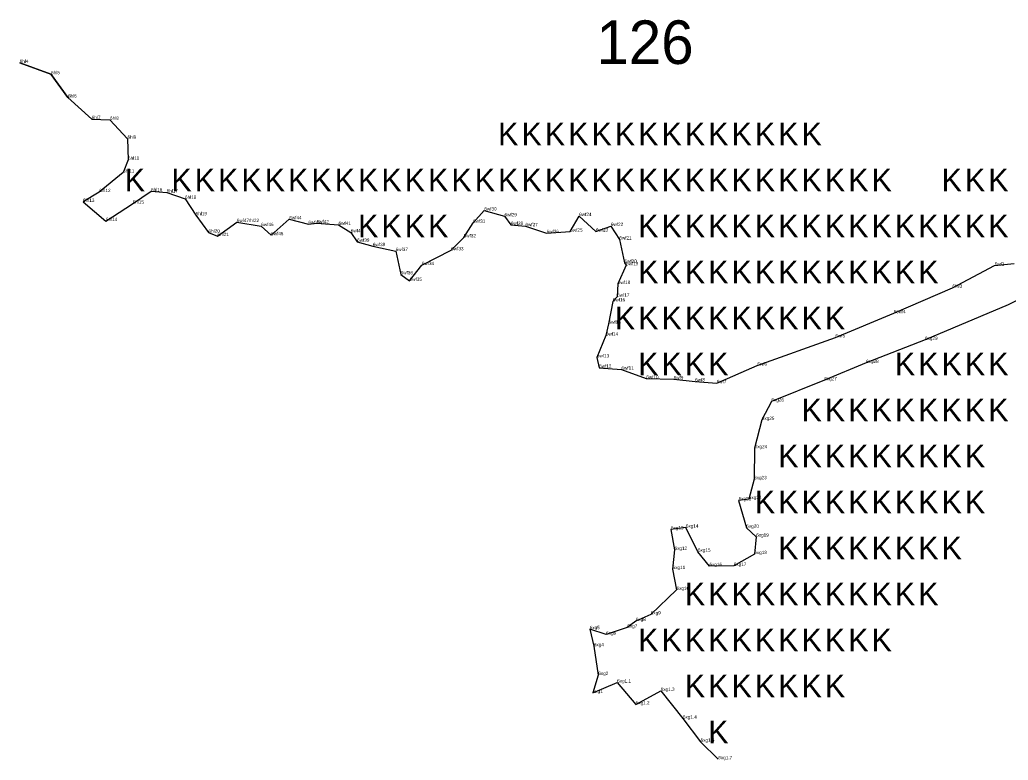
# Model space of a CAD drawing. Extents: x 2072529 to 2268812, y 436423 to 470008.
# Drawn here: x 2151885 to 2153367, y 437861 to 438972 of the extents above; entities that cross this region are included whole.
import ezdxf

# ---------------------------------------------------------------- set-up
doc = ezdxf.new("R2010")
doc.units = 0
for name, color, linetype in [('Old_Level_20', 7, 'Continuous'), ('Old_Level_52', 7, 'Continuous'), ('Old_Level_55', 7, 'Continuous'), ('Old_Level_60', 7, 'Continuous'), ('Old_Level_62', 7, 'Continuous')]:
    doc.layers.add(name, color=color, linetype=linetype)

msp = doc.modelspace()

# ---------------------------------------------------------------- linework, layer by layer
at = {"layer": 'Old_Level_20'}
for p, q in [((2151932.086, 438889.94), (2151932.086, 438889.94)), ((2151932.086, 438889.94), (2151932.086, 438889.94)), ((2151932.086, 438889.94), (2151932.086, 438889.94)), ((2151957.305, 438854.948), (2151957.305, 438854.948)), ((2151957.305, 438854.948), (2151957.305, 438854.948)), ((2151957.305, 438854.948), (2151957.305, 438854.948)), ((2151993.082, 438822.703), (2151993.082, 438822.703)), ((2151993.082, 438822.703), (2151993.082, 438822.703)), ((2151993.082, 438822.703), (2151993.082, 438822.703)), ((2152020.361, 438821.547), (2152020.361, 438821.547)), ((2152046.757, 438793.156), (2152046.757, 438793.156)), ((2152047.495, 438761.53), (2152047.495, 438761.53)), ((2152040.01, 438742.313), (2152040.01, 438742.313)), ((2152004.377, 438713.058), (2152004.377, 438713.058)), ((2152082.016, 438714.429), (2152082.016, 438714.429)), ((2152105.432, 438712.49), (2152105.432, 438712.49)), ((2152132.925, 438703.042), (2152132.925, 438703.042)), ((2151980.215, 438698.474), (2151980.215, 438698.474)), ((2152054.394, 438695.734), (2152054.394, 438695.734)), ((2152148.934, 438678.389), (2152148.934, 438678.389)), ((2152289.336, 438672.405), (2152289.336, 438672.405)), ((2152581.734, 438685.505), (2152581.734, 438685.505)), ((2152581.734, 438685.505), (2152581.734, 438685.505)), ((2152612.078, 438676.759), (2152612.078, 438676.759)), ((2152612.078, 438676.759), (2152612.078, 438676.759)), ((2152724.008, 438677.199), (2152724.008, 438677.199)), ((2152724.008, 438677.199), (2152724.008, 438677.199)), ((2152014.374, 438669.681), (2152014.374, 438669.681)), ((2152210.534, 438668.162), (2152210.534, 438668.162)), ((2152247.263, 438662.066), (2152247.263, 438662.066)), ((2152318.015, 438665.179), (2152318.015, 438665.179)), ((2152330.374, 438666.368), (2152330.374, 438666.368)), ((2152363.146, 438663.945), (2152363.146, 438663.945)), ((2152564.875, 438667.018), (2152564.875, 438667.018)), ((2152564.875, 438667.018), (2152564.875, 438667.018)), ((2152621.518, 438663.89), (2152621.518, 438663.89)), ((2152621.518, 438663.89), (2152621.518, 438663.89)), ((2152643.46, 438661.979), (2152643.46, 438661.979)), ((2152643.46, 438661.979), (2152643.46, 438661.979)), ((2152771.592, 438662.228), (2152771.592, 438662.228)), ((2152771.592, 438662.228), (2152771.592, 438662.228)), ((2152168.125, 438652.279), (2152168.125, 438652.279)), ((2152181.615, 438647.155), (2152181.615, 438647.155)), ((2152262.029, 438648.427), (2152262.029, 438648.427)), ((2152381.634, 438652.722), (2152381.634, 438652.722)), ((2152550.829, 438645.221), (2152550.829, 438645.221)), ((2152675.24, 438651.608), (2152675.24, 438651.608)), ((2152675.24, 438651.608), (2152675.24, 438651.608)), ((2152710.662, 438653.779), (2152710.662, 438653.779)), ((2152710.662, 438653.779), (2152710.662, 438653.779)), ((2152749.073, 438653.975), (2152749.073, 438653.975)), ((2152749.073, 438653.975), (2152749.073, 438653.975)), ((2152391.045, 438638.562), (2152391.045, 438638.562)), ((2152414.676, 438632.035), (2152414.676, 438632.035)), ((2152784.294, 438641.972), (2152784.294, 438641.972)), ((2152784.294, 438641.972), (2152784.294, 438641.972)), ((2152448.851, 438624.645), (2152448.851, 438624.645)), ((2152532.123, 438625.806), (2152532.123, 438625.806)), ((2152487.971, 438603.621), (2152487.971, 438603.621)), ((2152791.953, 438607.04), (2152791.953, 438607.04)), ((2152791.953, 438607.04), (2152791.953, 438607.04)), ((2152794.25, 438603.326), (2152794.25, 438603.326)), ((2152794.25, 438603.326), (2152794.25, 438603.326)), ((2153347.104, 438602.749), (2153347.104, 438602.749)), ((2153347.104, 438602.749), (2153347.104, 438602.749)), ((2152456.335, 438589.708), (2152456.335, 438589.708)), ((2152469.745, 438579.89), (2152469.745, 438579.89)), ((2152782.155, 438575.242), (2152782.155, 438575.242)), ((2152782.155, 438575.242), (2152782.155, 438575.242)), ((2153283.767, 438569.533), (2153283.767, 438569.533)), ((2153283.767, 438569.533), (2153283.767, 438569.533)), ((2152780.938, 438556.129), (2152780.938, 438556.129)), ((2152780.938, 438556.129), (2152780.938, 438556.129)), ((2152774.499, 438549.053), (2152774.499, 438549.053)), ((2152774.499, 438549.053), (2152774.499, 438549.053)), ((2153367.204, 438544.182), (2153367.204, 438544.182)), ((2153367.204, 438544.182), (2153367.204, 438544.182)), ((2153195.696, 438531.422), (2153195.696, 438531.422)), ((2153195.696, 438531.422), (2153195.696, 438531.422)), ((2152768.005, 438515.577), (2152768.005, 438515.577)), ((2152768.005, 438515.577), (2152768.005, 438515.577)), ((2152764.057, 438497.915), (2152764.057, 438497.915)), ((2152764.057, 438497.915), (2152764.057, 438497.915)), ((2153108.314, 438495.075), (2153108.314, 438495.075)), ((2153108.314, 438495.075), (2153108.314, 438495.075)), ((2153242.688, 438491.329), (2153242.688, 438491.329)), ((2153242.688, 438491.329), (2153242.688, 438491.329)), ((2152750.57, 438465.117), (2152750.57, 438465.117)), ((2152750.57, 438465.117), (2152750.57, 438465.117)), ((2152991.182, 438452.732), (2152991.182, 438452.732)), ((2152991.182, 438452.732), (2152991.182, 438452.732)), ((2153154.34, 438456.737), (2153154.34, 438456.737)), ((2153154.34, 438456.737), (2153154.34, 438456.737)), ((2152753.945, 438449.479), (2152753.945, 438449.479)), ((2152753.945, 438449.479), (2152753.945, 438449.479)), ((2152787.432, 438446.808), (2152787.432, 438446.808)), ((2152787.432, 438446.808), (2152787.432, 438446.808)), ((2152824.61, 438433.245), (2152824.61, 438433.245)), ((2152824.61, 438433.245), (2152824.61, 438433.245)), ((2152865.742, 438432.251), (2152865.742, 438432.251)), ((2152865.742, 438432.251), (2152865.742, 438432.251)), ((2152898.033, 438429.104), (2152898.033, 438429.104)), ((2152898.033, 438429.104), (2152898.033, 438429.104)), ((2152930.298, 438426.43), (2152930.298, 438426.43)), ((2152930.298, 438426.43), (2152930.298, 438426.43)), ((2153091.7, 438430.776), (2153091.7, 438430.776)), ((2153091.7, 438430.776), (2153091.7, 438430.776)), ((2153012.335, 438399.042), (2153012.335, 438399.042)), ((2153012.335, 438399.042), (2153012.335, 438399.042)), ((2152997.951, 438371.198), (2152997.951, 438371.198)), ((2152997.951, 438371.198), (2152997.951, 438371.198)), ((2152987.155, 438328.86), (2152987.155, 438328.86)), ((2152987.155, 438328.86), (2152987.155, 438328.86)), ((2152986.406, 438282.382), (2152986.406, 438282.382)), ((2152963.156, 438250.664), (2152963.156, 438250.664)), ((2152963.156, 438250.664), (2152963.156, 438250.664)), ((2152978.542, 438252.567), (2152978.542, 438252.567)), ((2152978.542, 438252.567), (2152978.542, 438252.567)), ((2152861.659, 438207.013), (2152861.659, 438207.013)), ((2152884.089, 438209.695), (2152884.089, 438209.695)), ((2152974.724, 438209.477), (2152974.724, 438209.477)), ((2152989.516, 438196.131), (2152989.516, 438196.131)), ((2152867.037, 438176.333), (2152867.037, 438176.333)), ((2152902.145, 438173.614), (2152902.145, 438173.614)), ((2152986.751, 438169.992), (2152986.751, 438169.992)), ((2152864.209, 438147.493), (2152864.209, 438147.493)), ((2152919.475, 438152.053), (2152919.475, 438152.053)), ((2152955.913, 438152.287), (2152955.913, 438152.287)), ((2152870.127, 438116.252), (2152870.127, 438116.252)), ((2152831.412, 438079.453), (2152831.412, 438079.453)), ((2152808.876, 438069.543), (2152808.876, 438069.543)), ((2152739.839, 438057.4), (2152739.839, 438057.4)), ((2152796.184, 438059.668), (2152796.184, 438059.668)), ((2152764.476, 438049.22), (2152764.476, 438049.22)), ((2152746.063, 438031.735), (2152746.063, 438031.735)), ((2152752.743, 437988.598), (2152752.743, 437988.598)), ((2152781.014, 437977.361), (2152781.014, 437977.361)), ((2152744.406, 437961.649), (2152744.406, 437961.649)), ((2152846.292, 437964.803), (2152846.292, 437964.803)), ((2152808.819, 437944.371), (2152808.819, 437944.371)), ((2152879.617, 437923.16), (2152879.617, 437923.16)), ((2152906.084, 437888.466), (2152906.084, 437888.466)), ((2152932.71, 437862.245), (2152932.71, 437862.245))]:
    msp.add_line(p, q, dxfattribs=at)
at = {"layer": 'Old_Level_52'}
for p, q in [((2151931.796, 438890.045), (2151885.108, 438906.961)), ((2151885.108, 438906.961), (2151931.796, 438890.045)), ((2151957.243, 438855.035), (2151932.266, 438889.69)), ((2151932.266, 438889.69), (2151957.243, 438855.035)), ((2151993.082, 438822.703), (2151957.384, 438854.877)), ((2151957.384, 438854.877), (2151993.082, 438822.703))]:
    msp.add_line(p, q, dxfattribs=at)
for points in [[(2151993.082, 438822.703), (2152020.361, 438821.547), (2152046.757, 438793.156), (2152047.495, 438761.53), (2152040.01, 438742.313), (2152004.377, 438713.058), (2151980.215, 438698.474), (2152014.374, 438669.681), (2152054.394, 438695.734), (2152082.016, 438714.429), (2152105.432, 438712.49), (2152132.925, 438703.042), (2152148.934, 438678.389), (2152168.125, 438652.279), (2152181.615, 438647.155), (2152210.534, 438668.162), (2152247.263, 438662.066), (2152262.029, 438648.427), (2152289.336, 438672.405), (2152318.015, 438665.179), (2152330.374, 438666.368), (2152363.146, 438663.945), (2152381.634, 438652.722), (2152391.045, 438638.562), (2152414.676, 438632.035), (2152448.851, 438624.645), (2152456.335, 438589.708)], [(2152564.875, 438667.018), (2152581.734, 438685.505), (2152612.078, 438676.759), (2152621.518, 438663.89), (2152643.46, 438661.979), (2152675.24, 438651.608), (2152710.662, 438653.779), (2152724.008, 438677.199), (2152749.073, 438653.975), (2152771.592, 438662.228), (2152784.294, 438641.972), (2152791.953, 438607.04), (2152794.25, 438603.326), (2152782.155, 438575.242), (2152780.938, 438556.129), (2152774.499, 438549.053), (2152768.005, 438515.577), (2152764.057, 438497.915), (2152750.57, 438465.117), (2152753.945, 438449.479), (2152787.432, 438446.808), (2152824.61, 438433.245), (2152865.742, 438432.251), (2152898.033, 438429.104), (2152930.298, 438426.43), (2152991.182, 438452.732), (2153108.314, 438495.075), (2153195.696, 438531.422), (2153283.767, 438569.533), (2153347.104, 438602.749), (2153376.256, 438606.208)], [(2152456.335, 438589.708), (2152469.745, 438579.89), (2152487.971, 438603.621), (2152532.123, 438625.806), (2152550.829, 438645.221), (2152564.875, 438667.018)], [(2153400.268, 438560.674), (2153367.204, 438544.182), (2153242.688, 438491.329), (2153154.34, 438456.737), (2153091.7, 438430.776), (2153012.335, 438399.042), (2152997.951, 438371.198), (2152987.155, 438328.86), (2152986.406, 438282.382), (2152978.542, 438252.567), (2152963.156, 438250.664)], [(2152963.156, 438250.664), (2152974.724, 438209.477), (2152989.516, 438196.131), (2152986.751, 438169.992), (2152955.913, 438152.287), (2152919.475, 438152.053), (2152902.145, 438173.614), (2152884.089, 438209.695), (2152861.659, 438207.013), (2152867.037, 438176.333), (2152864.209, 438147.493), (2152870.127, 438116.252), (2152831.412, 438079.453), (2152808.876, 438069.543), (2152796.184, 438059.668), (2152764.476, 438049.22), (2152739.839, 438057.4), (2152746.063, 438031.735), (2152752.743, 437988.598), (2152744.406, 437961.649)], [(2152744.406, 437961.649), (2152781.014, 437977.361), (2152808.819, 437944.371), (2152846.292, 437964.803), (2152879.617, 437923.16), (2152906.084, 437888.466), (2152932.71, 437862.245)]]:
    msp.add_lwpolyline(points, dxfattribs=at)
for centre, start, end in [((2151931.455, 438889.105), 35.780578, 70.083561), ((2151931.455, 438889.105), 35.780578, 70.083561), ((2151958.054, 438855.619), 215.780578, 227.972378)]:
    msp.add_arc(centre, 1, start, end, dxfattribs=at)

# ---------------------------------------------------------------- texts
at = {"layer": 'Old_Level_55'}
for p in [(2152602.561, 438783.297), (2152637.561, 438783.297), (2152672.561, 438783.297), (2152707.561, 438783.297), (2152742.561, 438783.297), (2152777.561, 438783.297), (2152812.561, 438783.297), (2152847.561, 438783.297), (2152882.561, 438783.297), (2152917.561, 438783.297), (2152952.561, 438783.297), (2152987.561, 438783.297), (2153022.561, 438783.297), (2153057.561, 438783.297), (2152042.561, 438714.297), (2152112.561, 438714.297), (2152147.561, 438714.297), (2152182.561, 438714.297), (2152217.561, 438714.297), (2152252.561, 438714.297), (2152287.561, 438714.297), (2152322.561, 438714.297), (2152357.561, 438714.297), (2152392.561, 438714.297), (2152427.561, 438714.297), (2152462.561, 438714.297), (2152497.561, 438714.297), (2152532.561, 438714.297), (2152567.561, 438714.297), (2152602.561, 438714.297), (2152637.561, 438714.297), (2152672.561, 438714.297), (2152707.561, 438714.297), (2152742.561, 438714.297), (2152777.561, 438714.297), (2152812.561, 438714.297), (2152847.561, 438714.297), (2152882.561, 438714.297), (2152917.561, 438714.297), (2152952.561, 438714.297), (2152987.561, 438714.297), (2153022.561, 438714.297), (2153057.561, 438714.297), (2153092.561, 438714.297), (2153127.561, 438714.297), (2153162.561, 438714.297), (2153267.561, 438714.297), (2153302.561, 438714.297), (2153337.561, 438714.297), (2152392.561, 438645.297), (2152427.561, 438645.297), (2152462.561, 438645.297), (2152497.561, 438645.297), (2152812.561, 438645.297), (2152847.561, 438645.297), (2152882.561, 438645.297), (2152917.561, 438645.297), (2152952.561, 438645.297), (2152987.561, 438645.297), (2153022.561, 438645.297), (2153057.561, 438645.297), (2153092.561, 438645.297), (2153127.561, 438645.297), (2153162.561, 438645.297), (2153197.561, 438645.297), (2153232.561, 438645.297), (2153267.561, 438645.297), (2153302.561, 438645.297), (2153337.561, 438645.297), (2152812.561, 438576.297), (2152847.561, 438576.297), (2152882.561, 438576.297), (2152917.561, 438576.297), (2152952.561, 438576.297), (2152987.561, 438576.297), (2153022.561, 438576.297), (2153057.561, 438576.297), (2153092.561, 438576.297), (2153127.561, 438576.297), (2153162.561, 438576.297), (2153197.561, 438576.297), (2153232.561, 438576.297), (2152777.561, 438507.297), (2152812.561, 438507.297), (2152847.561, 438507.297), (2152882.561, 438507.297), (2152917.561, 438507.297), (2152952.561, 438507.297), (2152987.561, 438507.297), (2153022.561, 438507.297), (2153057.561, 438507.297), (2153092.561, 438507.297), (2152812.561, 438438.297), (2152847.561, 438438.297), (2152882.561, 438438.297), (2152917.561, 438438.297), (2153197.561, 438438.297), (2153232.561, 438438.297), (2153267.561, 438438.297), (2153302.561, 438438.297), (2153337.561, 438438.297), (2153057.561, 438369.297), (2153092.561, 438369.297), (2153127.561, 438369.297), (2153162.561, 438369.297), (2153197.561, 438369.297), (2153232.561, 438369.297), (2153267.561, 438369.297), (2153302.561, 438369.297), (2153337.561, 438369.297), (2153022.561, 438300.297), (2153057.561, 438300.297), (2153092.561, 438300.297), (2153127.561, 438300.297), (2153162.561, 438300.297), (2153197.561, 438300.297), (2153232.561, 438300.297), (2153267.561, 438300.297), (2153302.561, 438300.297), (2152987.561, 438231.297), (2153022.561, 438231.297), (2153057.561, 438231.297), (2153092.561, 438231.297), (2153127.561, 438231.297), (2153162.561, 438231.297), (2153197.561, 438231.297), (2153232.561, 438231.297), (2153267.561, 438231.297), (2153302.561, 438231.297), (2153022.561, 438162.297), (2153057.561, 438162.297), (2153092.561, 438162.297), (2153127.561, 438162.297), (2153162.561, 438162.297), (2153197.561, 438162.297), (2153232.561, 438162.297), (2153267.561, 438162.297), (2152882.561, 438093.297), (2152917.561, 438093.297), (2152952.561, 438093.297), (2152987.561, 438093.297), (2153022.561, 438093.297), (2153057.561, 438093.297), (2153092.561, 438093.297), (2153127.561, 438093.297), (2153162.561, 438093.297), (2153197.561, 438093.297), (2153232.561, 438093.297), (2152812.561, 438024.297), (2152847.561, 438024.297), (2152882.561, 438024.297), (2152917.561, 438024.297), (2152952.561, 438024.297), (2152987.561, 438024.297), (2153022.561, 438024.297), (2153057.561, 438024.297), (2153092.561, 438024.297), (2153127.561, 438024.297), (2153162.561, 438024.297), (2152882.561, 437955.297), (2152917.561, 437955.297), (2152952.561, 437955.297), (2152987.561, 437955.297), (2153022.561, 437955.297), (2153057.561, 437955.297), (2153092.561, 437955.297), (2152917.561, 437886.297)]:
    msp.add_text('K', height=34, dxfattribs=at).set_placement(p)
at = {"layer": 'Old_Level_60'}
for s, p in [('6hl4', (2151885.006, 438906.998)), ('6hl4', (2151885.006, 438906.998)), ('6hl4', (2151885.006, 438906.998)), ('6hl5', (2151932.086, 438889.94)), ('6hl5', (2151932.086, 438889.94)), ('6hl5', (2151932.086, 438889.94)), ('6hl6', (2151957.305, 438854.948)), ('6hl6', (2151957.305, 438854.948)), ('6hl6', (2151957.305, 438854.948)), ('6hl7', (2151993.082, 438822.703)), ('6hl7', (2151993.082, 438822.703)), ('6hl7', (2151993.082, 438822.703)), ('6hl8', (2152020.361, 438821.547)), ('6hl9', (2152046.757, 438793.156)), ('6hl10', (2152047.495, 438761.53)), ('6hl11', (2152040.01, 438742.313)), ('6hl12', (2152004.377, 438713.058)), ('6hl16', (2152082.016, 438714.429)), ('6hl17', (2152105.432, 438712.49)), ('6hl13', (2151980.215, 438698.474)), ('6hl18', (2152132.925, 438703.042)), ('6hl15', (2152054.394, 438695.734)), ('6wf30', (2152581.734, 438685.505)), ('6wf30', (2152581.734, 438685.505)), ('6hl14', (2152014.374, 438669.681)), ('6hl19', (2152148.934, 438678.389)), ('6wf47/hl22', (2152210.534, 438668.162)), ('6wf44', (2152289.336, 438672.405)), ('6wf29', (2152612.078, 438676.759)), ('6wf29', (2152612.078, 438676.759)), ('6wf24', (2152724.008, 438677.199)), ('6wf24', (2152724.008, 438677.199)), ('6hl20', (2152168.125, 438652.279)), ('6wf46', (2152247.263, 438662.066)), ('6wf43', (2152318.015, 438665.179)), ('6wf42', (2152330.374, 438666.368)), ('6wf41', (2152363.146, 438663.945)), ('6wf40', (2152381.634, 438652.722)), ('6wf31', (2152564.875, 438667.018)), ('6wf31', (2152564.875, 438667.018)), ('6wf28', (2152621.518, 438663.89)), ('6wf28', (2152621.518, 438663.89)), ('6wf27', (2152643.46, 438661.979)), ('6wf27', (2152643.46, 438661.979)), ('6wf25', (2152710.662, 438653.779)), ('6wf25', (2152710.662, 438653.779)), ('6wf23', (2152749.073, 438653.975)), ('6wf23', (2152749.073, 438653.975)), ('6wf22', (2152771.592, 438662.228)), ('6wf22', (2152771.592, 438662.228)), ('6hl21', (2152181.615, 438647.155)), ('6wf45', (2152262.029, 438648.427)), ('6wf39', (2152391.045, 438638.562)), ('6wf32', (2152550.829, 438645.221)), ('6wf26', (2152675.24, 438651.608)), ('6wf26', (2152675.24, 438651.608)), ('6wf21', (2152784.294, 438641.972)), ('6wf21', (2152784.294, 438641.972)), ('6wf38', (2152414.676, 438632.035)), ('6wf37', (2152448.851, 438624.645)), ('6wf33', (2152532.123, 438625.806)), ('6wf34', (2152487.971, 438603.621)), ('6wf20', (2152791.953, 438607.04)), ('6wf20', (2152791.953, 438607.04)), ('6wf19', (2152794.25, 438603.326)), ('6wf19', (2152794.25, 438603.326)), ('6wf2', (2153347.104, 438602.749)), ('6wf2', (2153347.104, 438602.749)), ('6wf36', (2152456.335, 438589.708)), ('6wf35', (2152469.745, 438579.89)), ('6wf18', (2152782.155, 438575.242)), ('6wf18', (2152782.155, 438575.242)), ('6fw3', (2153283.767, 438569.533)), ('6fw3', (2153283.767, 438569.533)), ('6wf16', (2152774.499, 438549.053)), ('6wf16', (2152774.499, 438549.053)), ('6wf17', (2152780.938, 438556.129)), ('6wf17', (2152780.938, 438556.129)), ('6swf4', (2153195.696, 438531.422)), ('6swf4', (2153195.696, 438531.422)), ('6wf15', (2152768.005, 438515.577)), ('6wf15', (2152768.005, 438515.577)), ('6wf14', (2152764.057, 438497.915)), ('6wf14', (2152764.057, 438497.915)), ('6wf5', (2153108.314, 438495.075)), ('6wf5', (2153108.314, 438495.075)), ('6xg29', (2153242.688, 438491.329)), ('6xg29', (2153242.688, 438491.329)), ('6wf13', (2152750.57, 438465.117)), ('6wf13', (2152750.57, 438465.117)), ('6wf12', (2152753.945, 438449.479)), ('6wf12', (2152753.945, 438449.479)), ('6wf11', (2152787.432, 438446.808)), ('6wf11', (2152787.432, 438446.808)), ('6wf6', (2152991.182, 438452.732)), ('6wf6', (2152991.182, 438452.732)), ('6xg28', (2153154.34, 438456.737)), ('6xg28', (2153154.34, 438456.737)), ('6wf10', (2152824.61, 438433.245)), ('6wf10', (2152824.61, 438433.245)), ('6wf9', (2152865.742, 438432.251)), ('6wf9', (2152865.742, 438432.251)), ('6xg27', (2153091.7, 438430.776)), ('6xg27', (2153091.7, 438430.776)), ('6wf8', (2152898.033, 438429.104)), ('6wf8', (2152898.033, 438429.104)), ('6wf7', (2152930.298, 438426.43)), ('6wf7', (2152930.298, 438426.43)), ('6xg26', (2153012.335, 438399.042)), ('6xg26', (2153012.335, 438399.042)), ('6xg25', (2152997.951, 438371.198)), ('6xg25', (2152997.951, 438371.198)), ('6xg24', (2152987.155, 438328.86)), ('6xg24', (2152987.155, 438328.86)), ('6xg23', (2152986.406, 438282.382)), ('6xg22', (2152978.542, 438252.567)), ('6xg22', (2152978.542, 438252.567)), ('6xg21', (2152963.156, 438250.664)), ('6xg21', (2152963.156, 438250.664)), ('6xg14', (2152884.089, 438209.695)), ('6xg20', (2152974.724, 438209.477)), ('6xg13', (2152861.659, 438207.013)), ('6xg19', (2152989.516, 438196.131)), ('6xg12', (2152867.037, 438176.333)), ('6xg15', (2152902.145, 438173.614)), ('6xg18', (2152986.751, 438169.992)), ('6xg16', (2152919.475, 438152.053)), ('6xg17', (2152955.913, 438152.287)), ('6xg11', (2152864.209, 438147.493)), ('6xg10', (2152870.127, 438116.252)), ('6xg9', (2152831.412, 438079.453)), ('6xg7', (2152796.184, 438059.668)), ('6xg8', (2152808.876, 438069.543)), ('6xg5', (2152739.839, 438057.4)), ('6xg6', (2152764.476, 438049.22)), ('6xg4', (2152746.063, 438031.735)), ('6xg2', (2152752.743, 437988.598)), ('6xg1.1', (2152781.014, 437977.361)), ('6xg1', (2152744.406, 437961.649)), ('6xg1.3', (2152846.292, 437964.803)), ('6xg1.2', (2152808.819, 437944.371)), ('6xg1.4', (2152879.617, 437923.16)), ('6xg1.6', (2152906.084, 437888.466)), ('6xg1.7', (2152932.71, 437862.245))]:
    msp.add_text(s, height=5, dxfattribs=at).set_placement(p)
at = {"layer": 'Old_Level_62'}
msp.add_text('126', height=65.34, dxfattribs=at).set_placement((2152749.853, 438905.361))

doc.saveas('drawing.dxf')
